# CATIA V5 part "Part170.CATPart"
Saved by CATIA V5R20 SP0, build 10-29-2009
Part number: FA 126700-1
Revision: ANY
Definition: UNKNOWN
Nomenclature: FA 126700-1
Source: Unknown
Bounding box of the stored display mesh (mm): x -3.804 to 3.804, y 0.2 to 2.5, z -4 to 4
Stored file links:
  C:\Users\Utente\Desktop\IO LAVORO\3D X SITO CF\CUMSA\3D files FA\FA 126700\Part170.CATPart
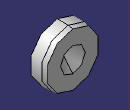
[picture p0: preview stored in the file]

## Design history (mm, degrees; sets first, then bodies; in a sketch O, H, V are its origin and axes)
Body1 "Cortar-Extruir1" (main body)
  Solid1: solid without history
